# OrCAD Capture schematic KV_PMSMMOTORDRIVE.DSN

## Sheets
1 TITLE PAGE: title: FRDM-MC-LVPMSM; rev: X1; company: Freescale Semiconductor; note: SCH-XXXXX PDF: SPF-XXXXX; note: 6501 William Cannon Drive West; note: Austin, TX 78735-8598
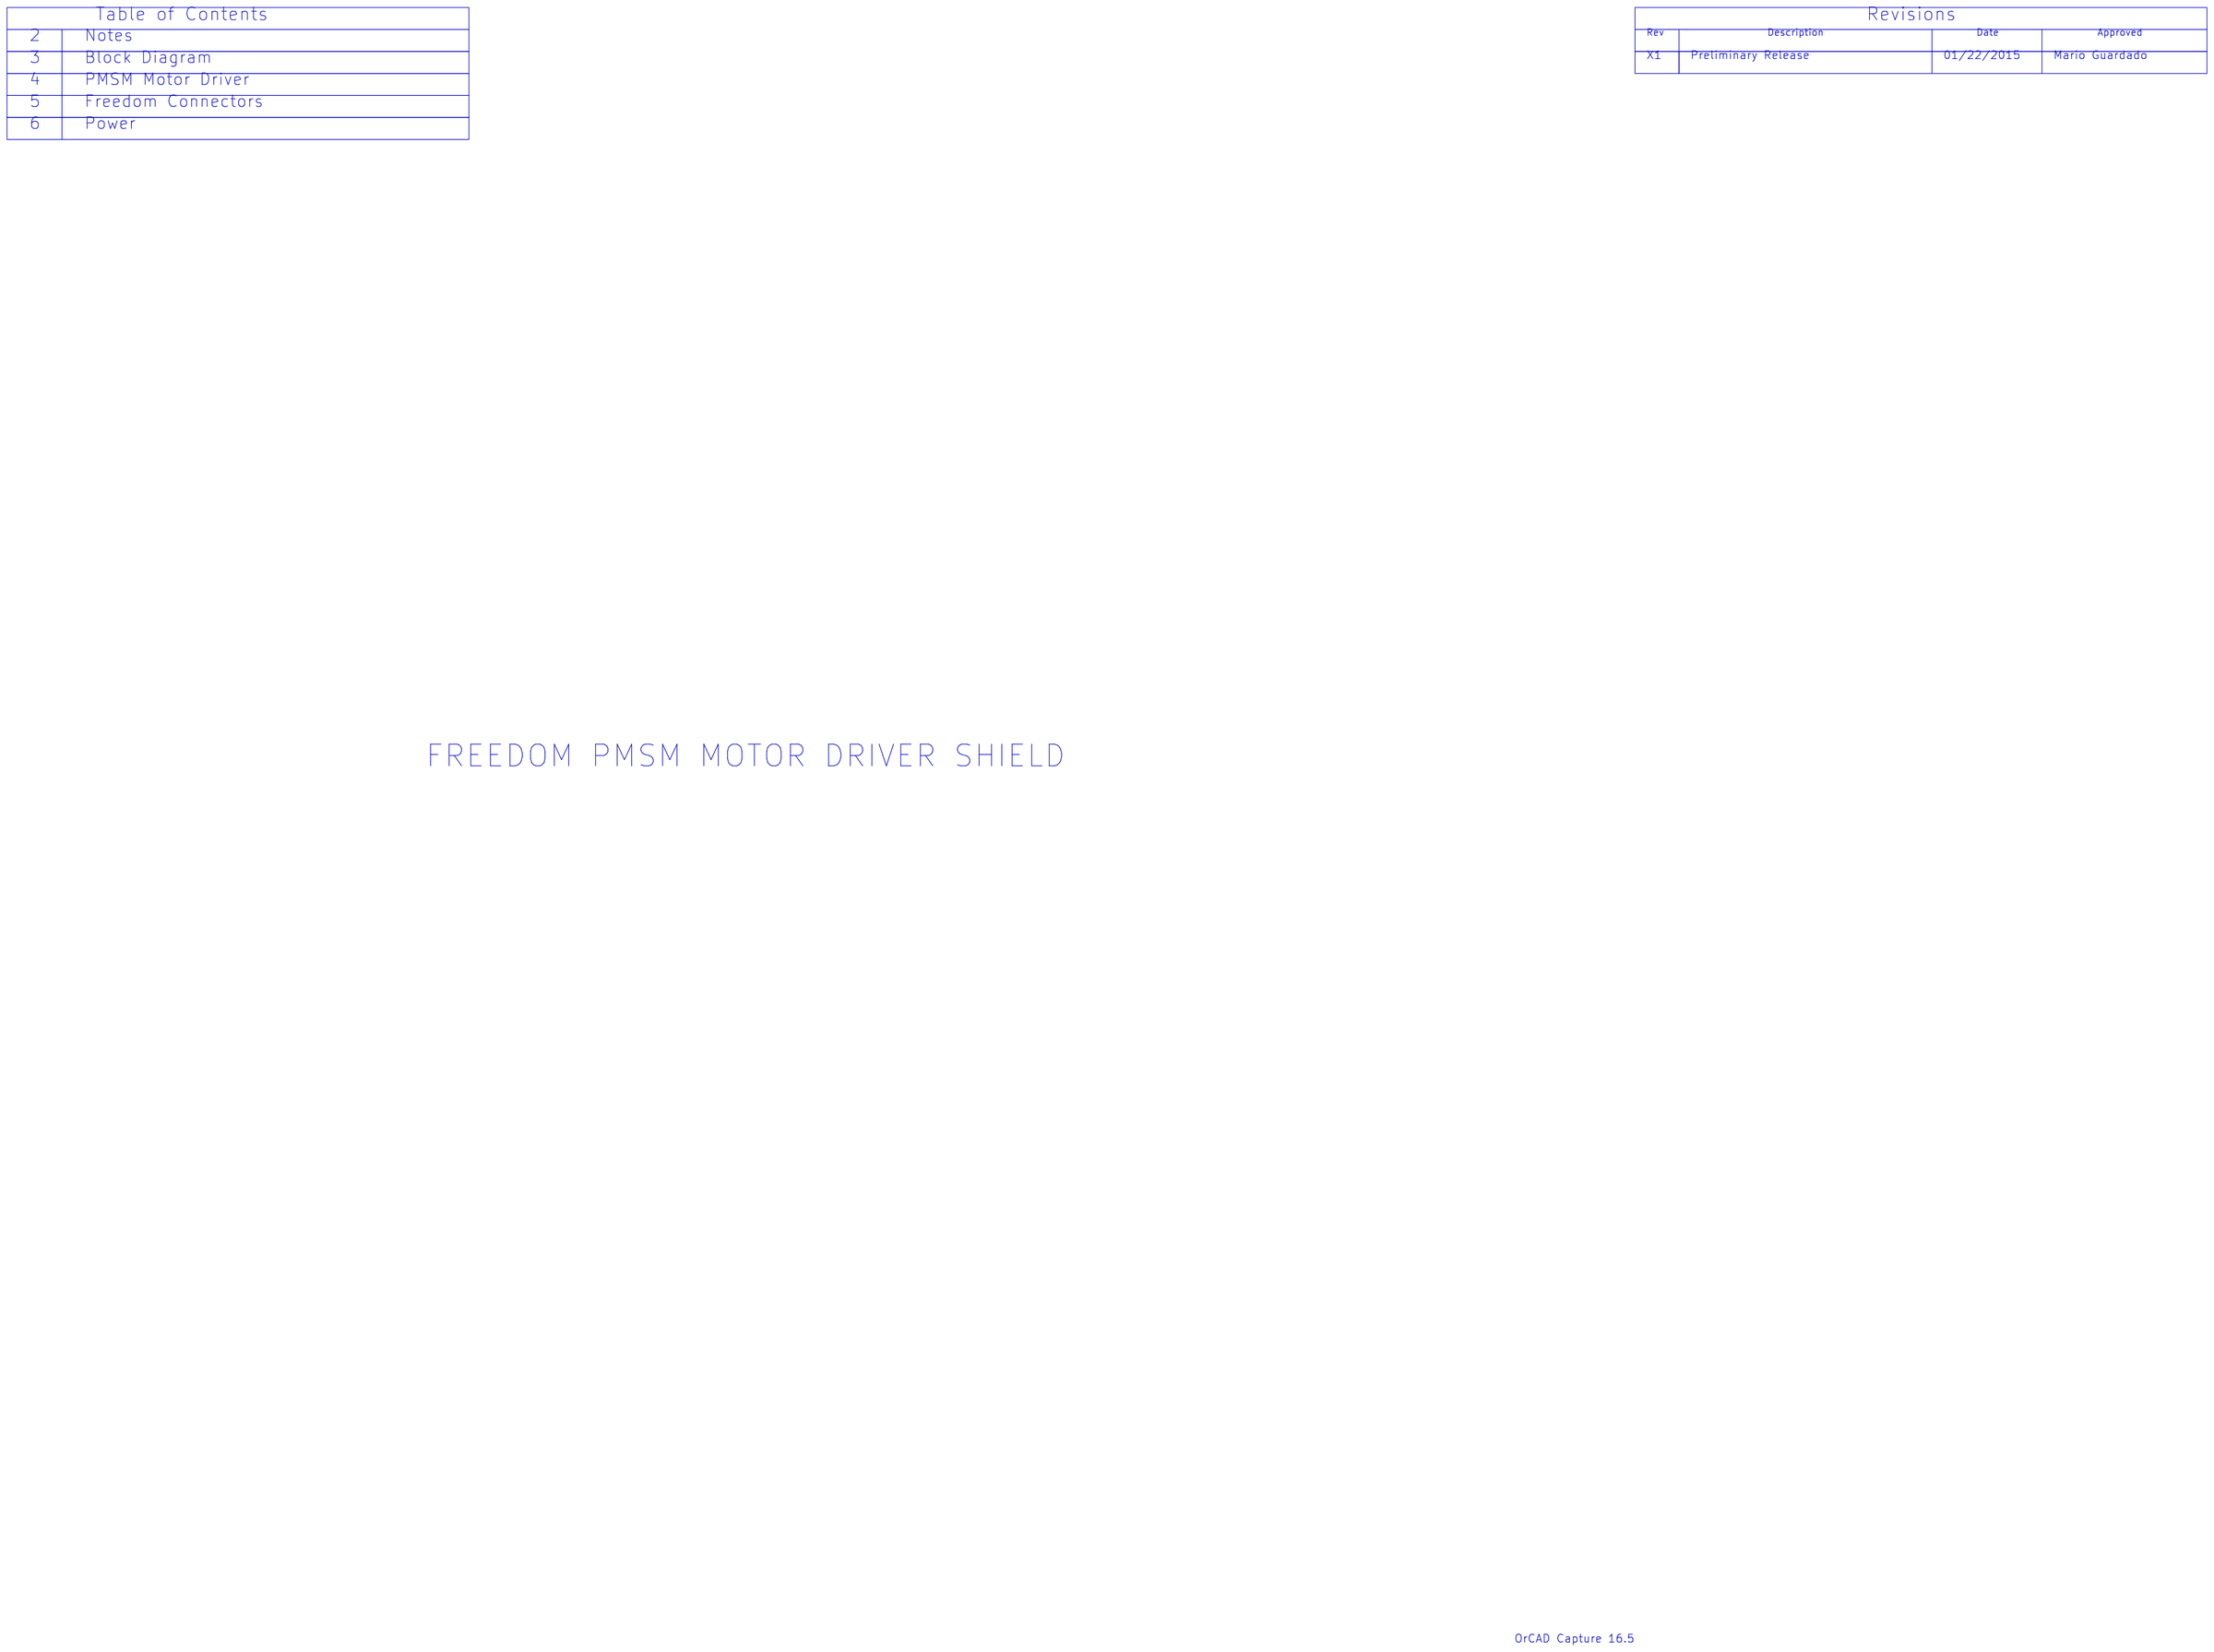
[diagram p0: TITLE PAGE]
2 NOTES
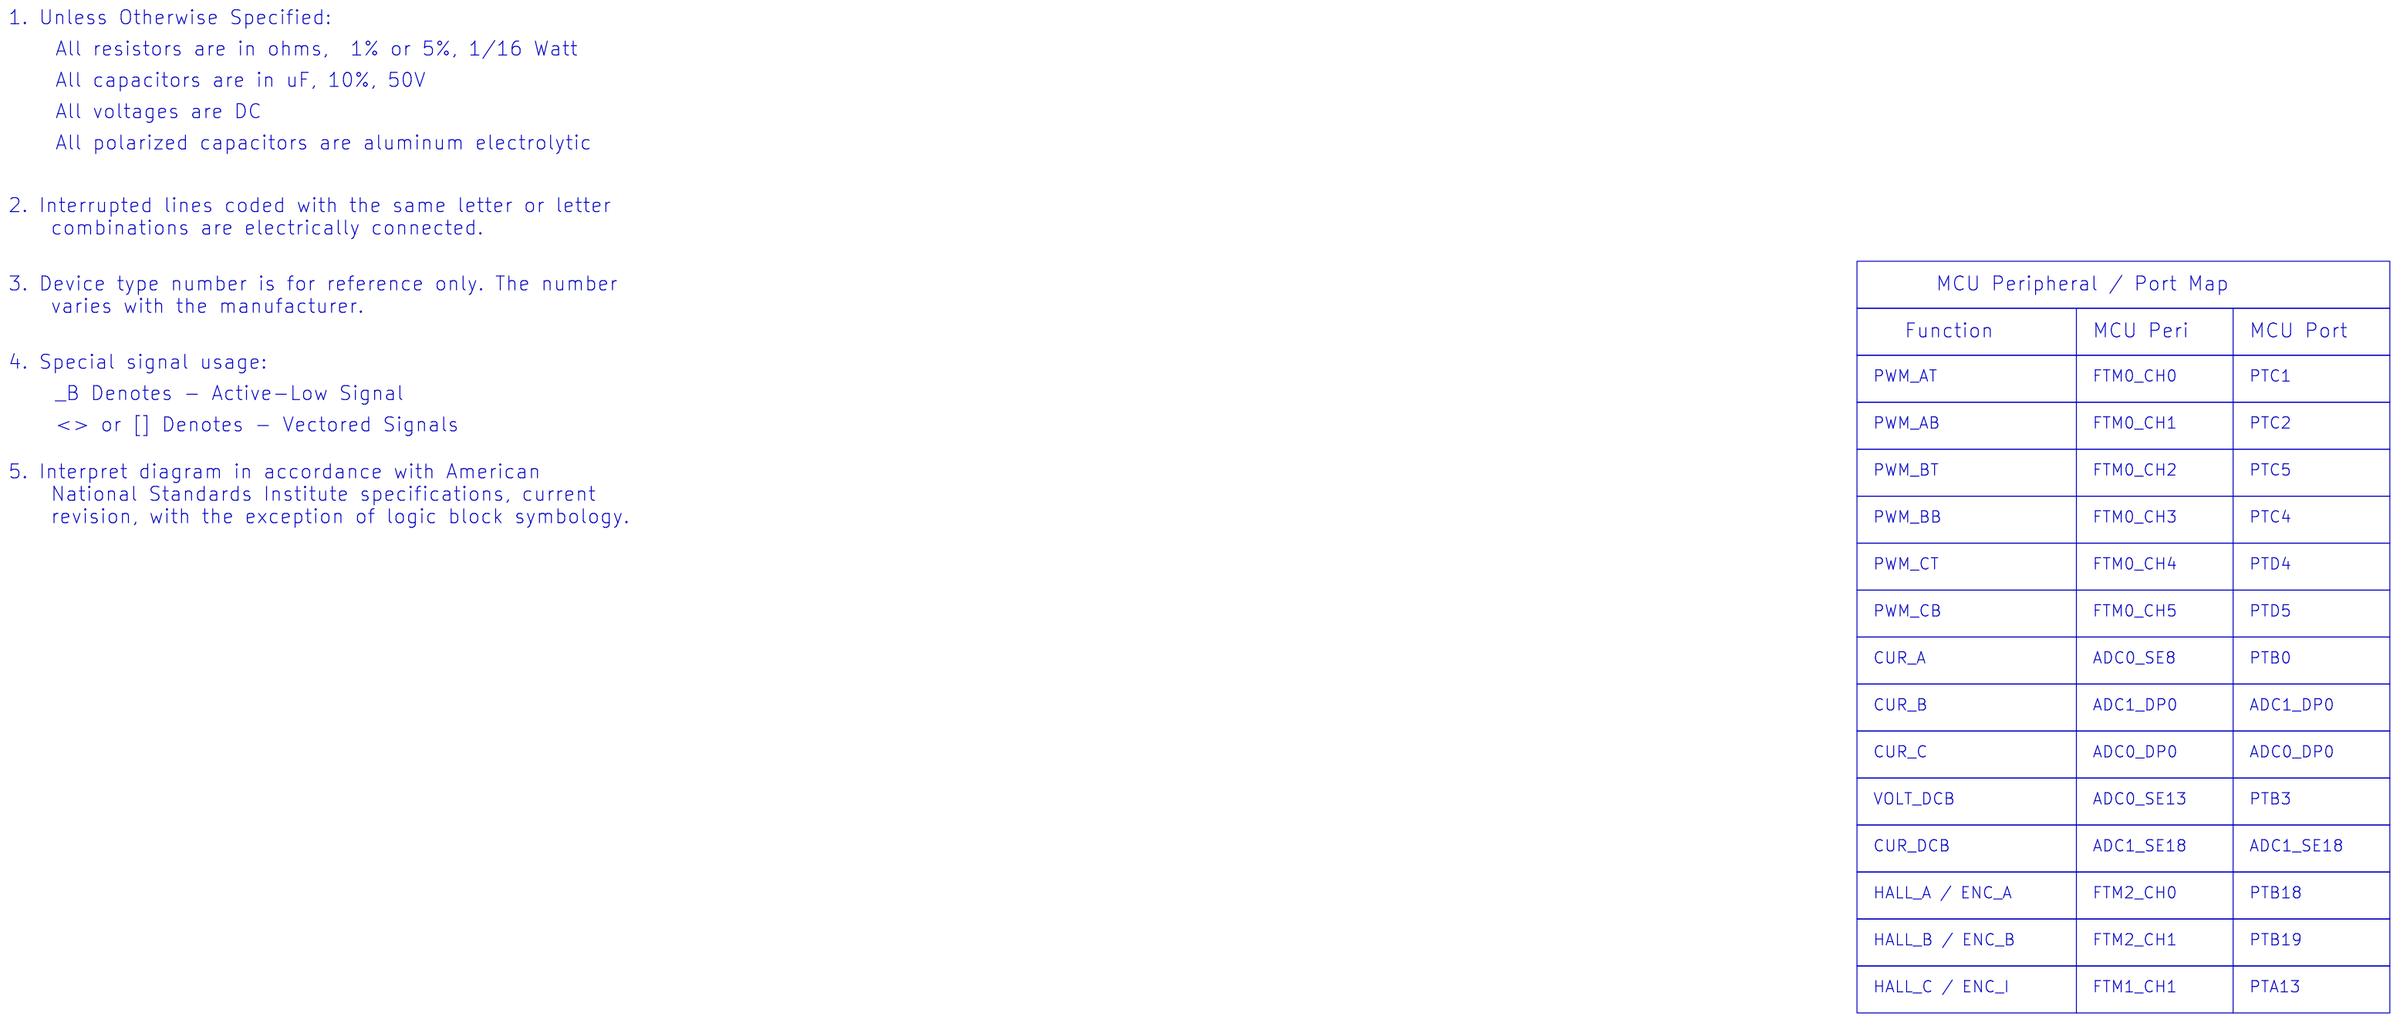
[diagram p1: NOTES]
3 BLOCK DIAGRAM
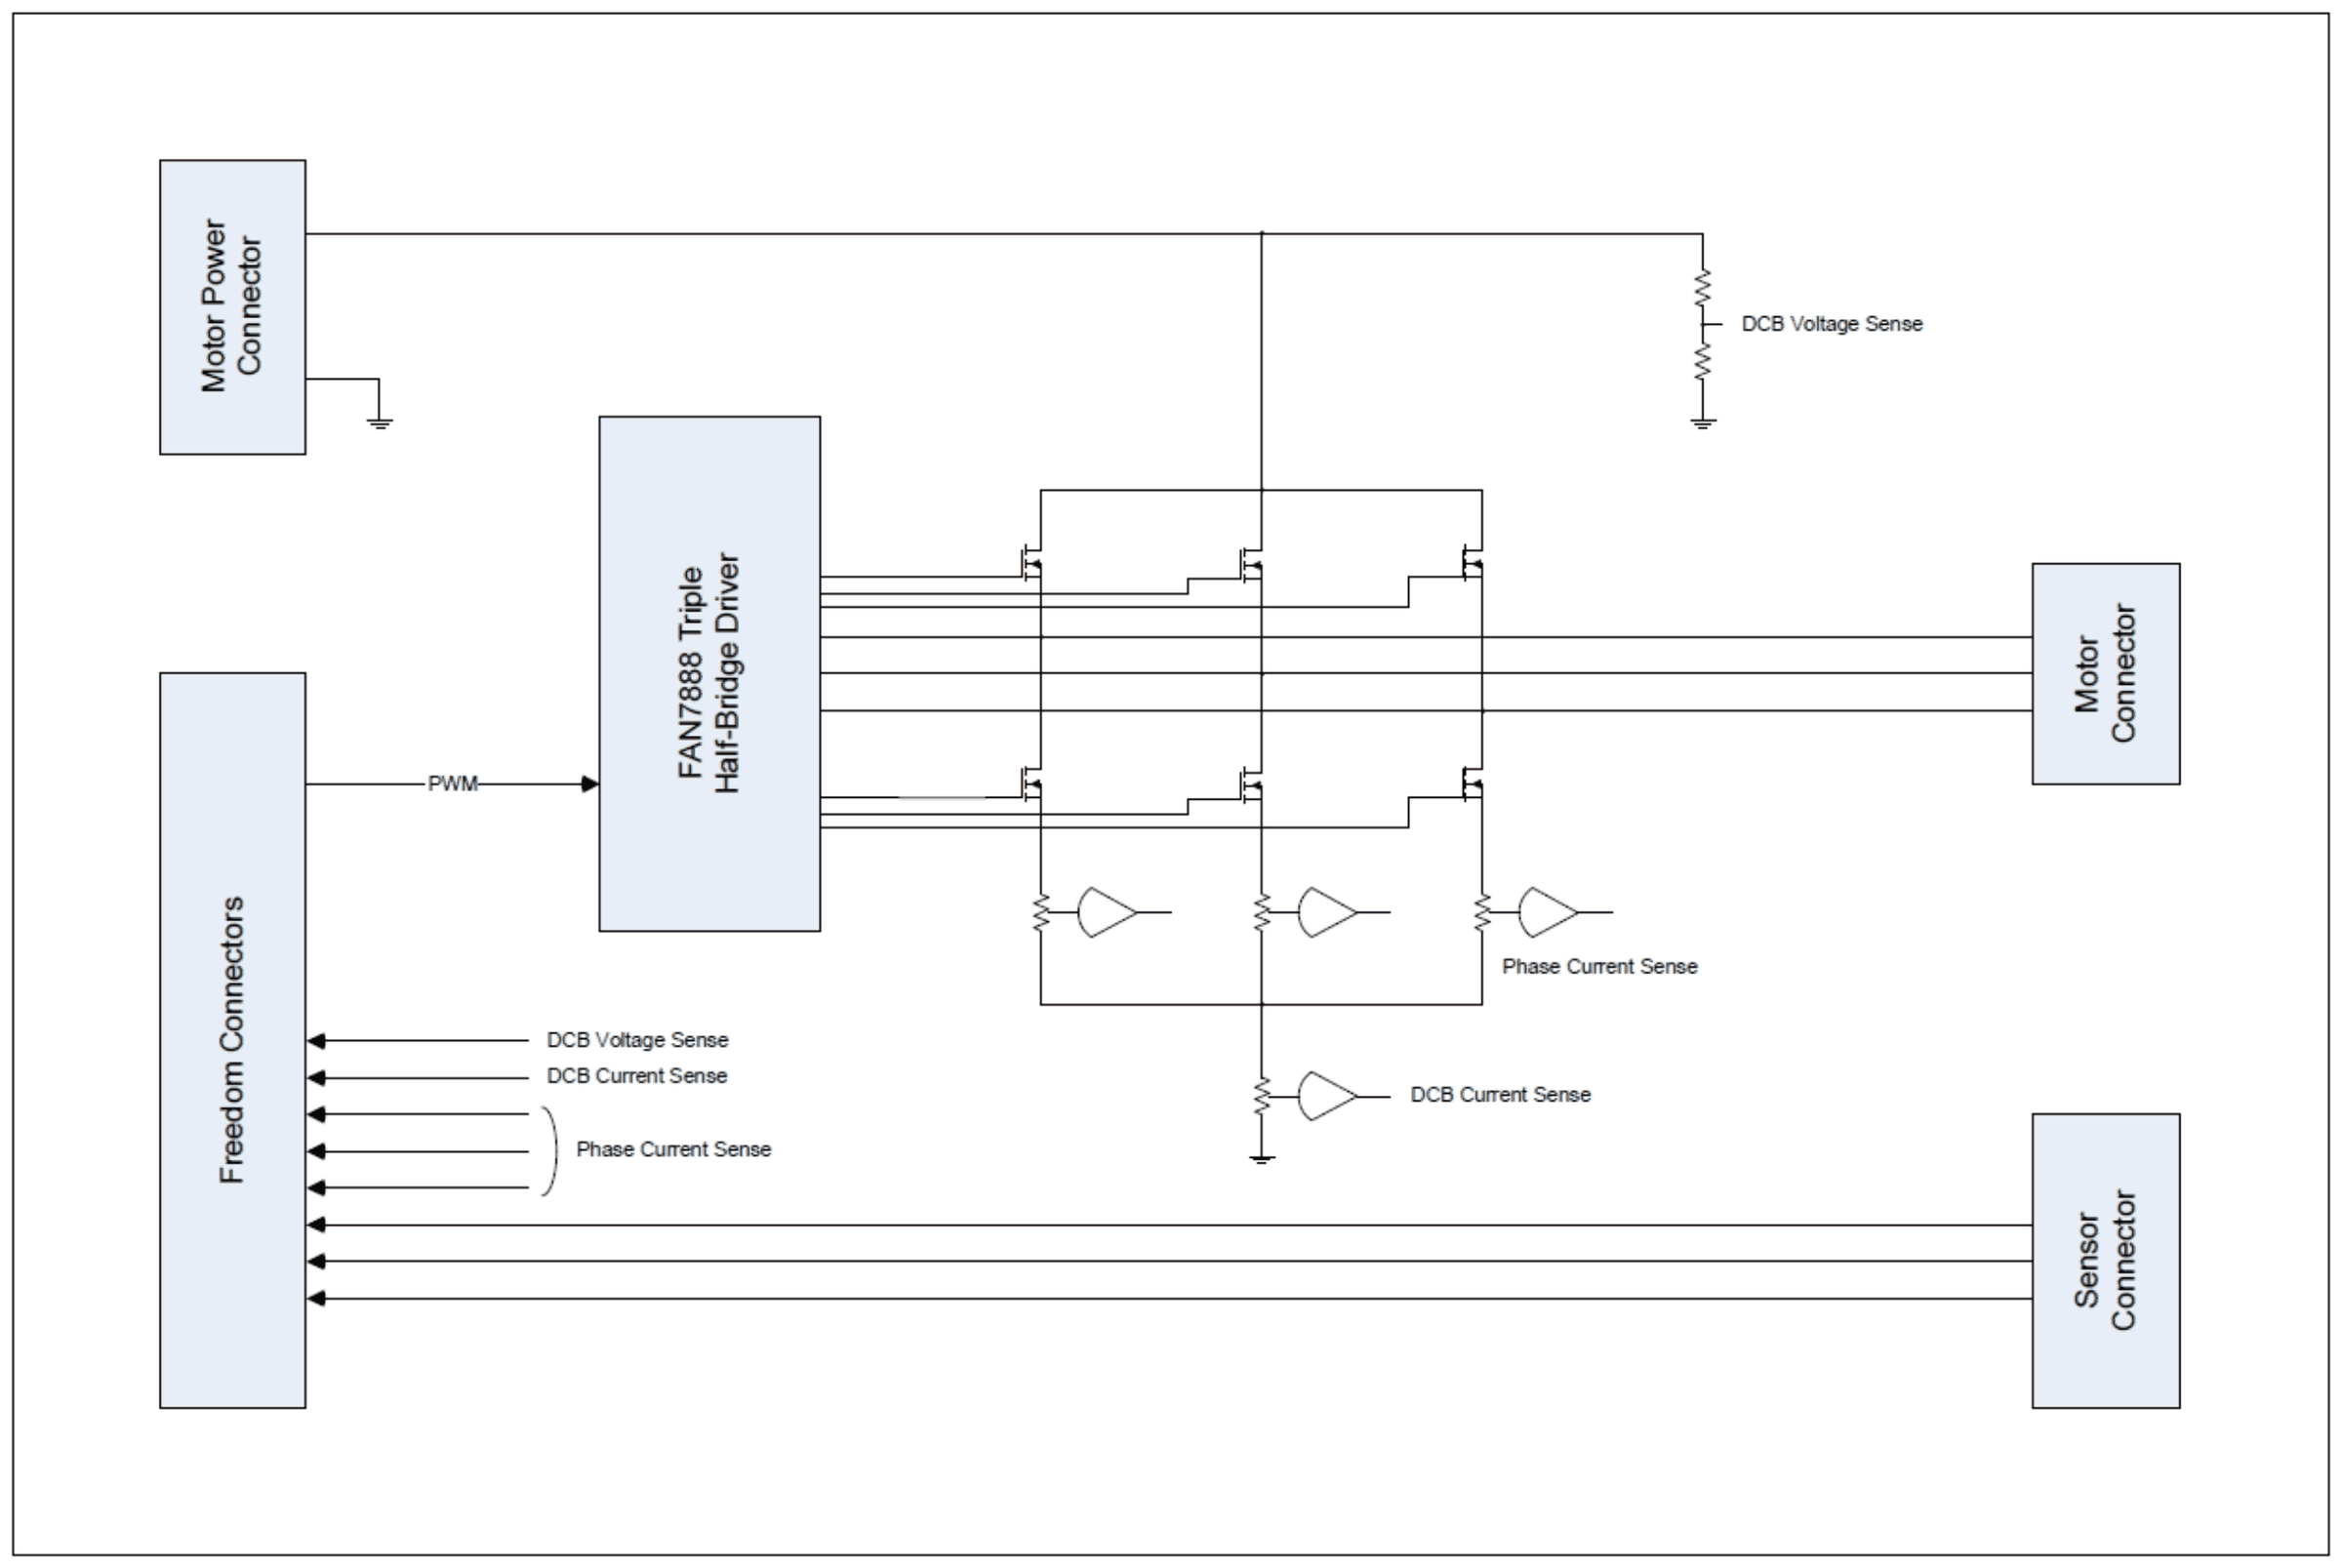
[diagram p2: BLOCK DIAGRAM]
4 MOTOR DRIVE: size C
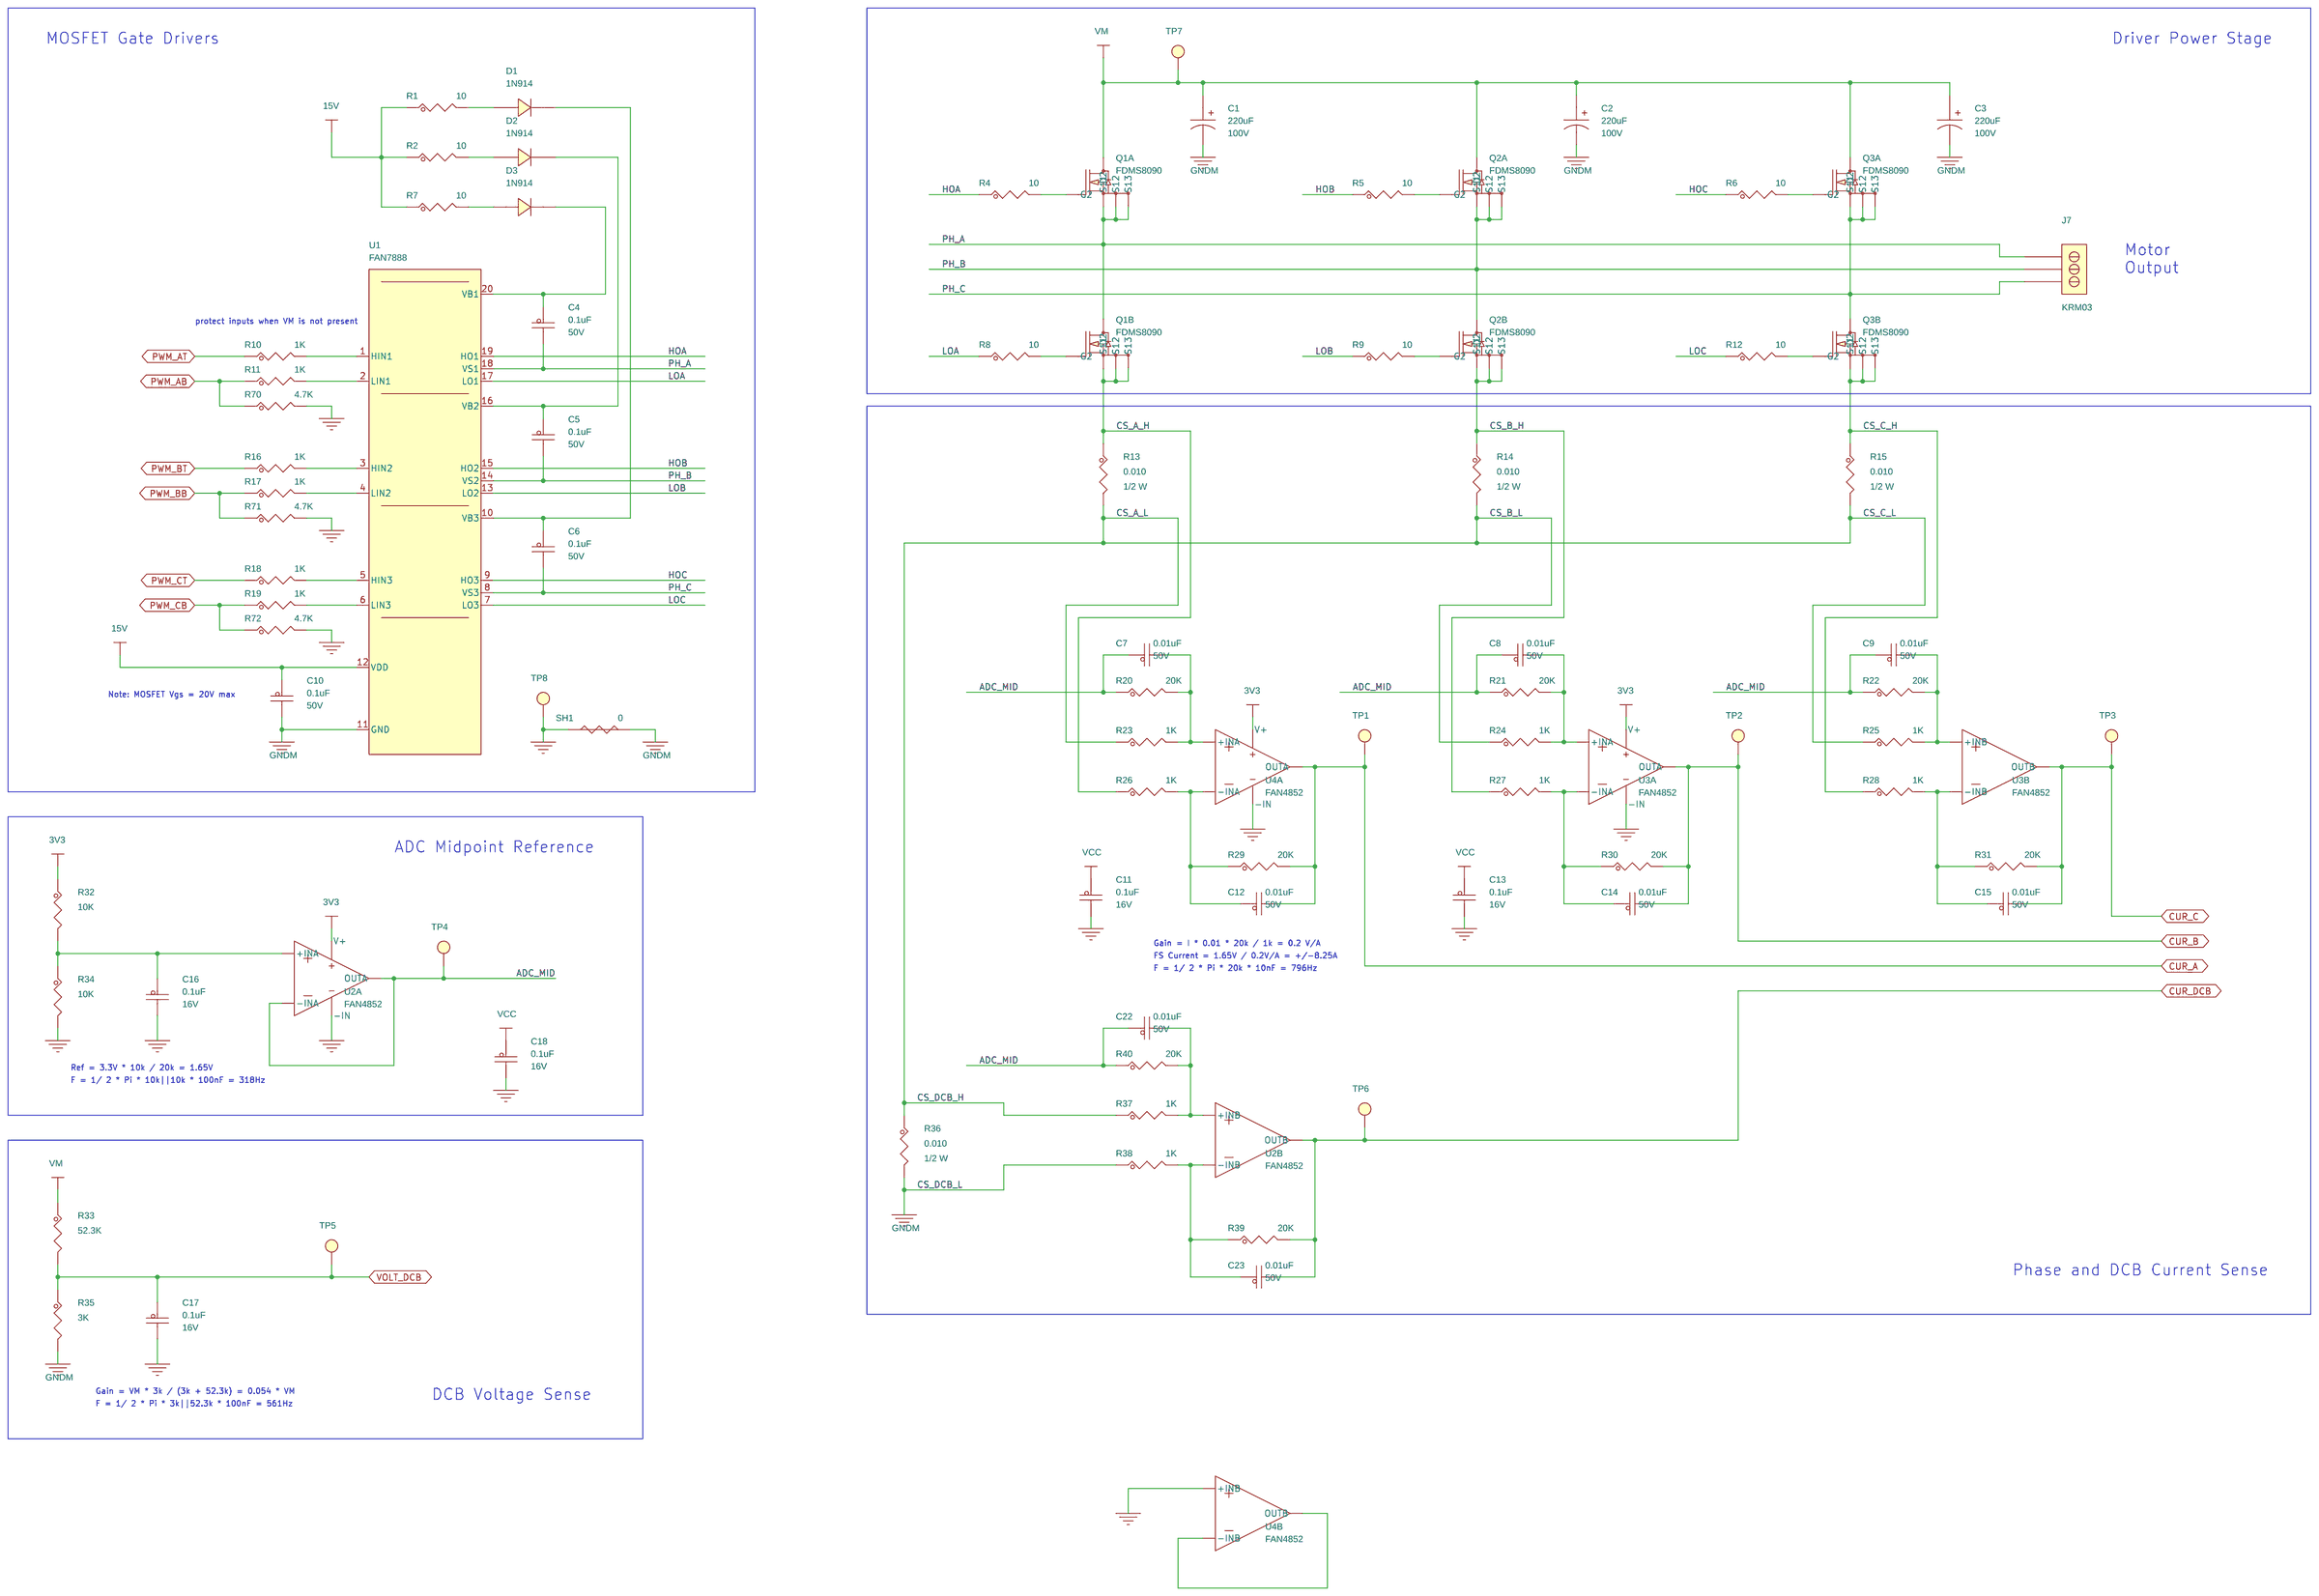
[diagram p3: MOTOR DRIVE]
5 MCU INTERFACE: size C
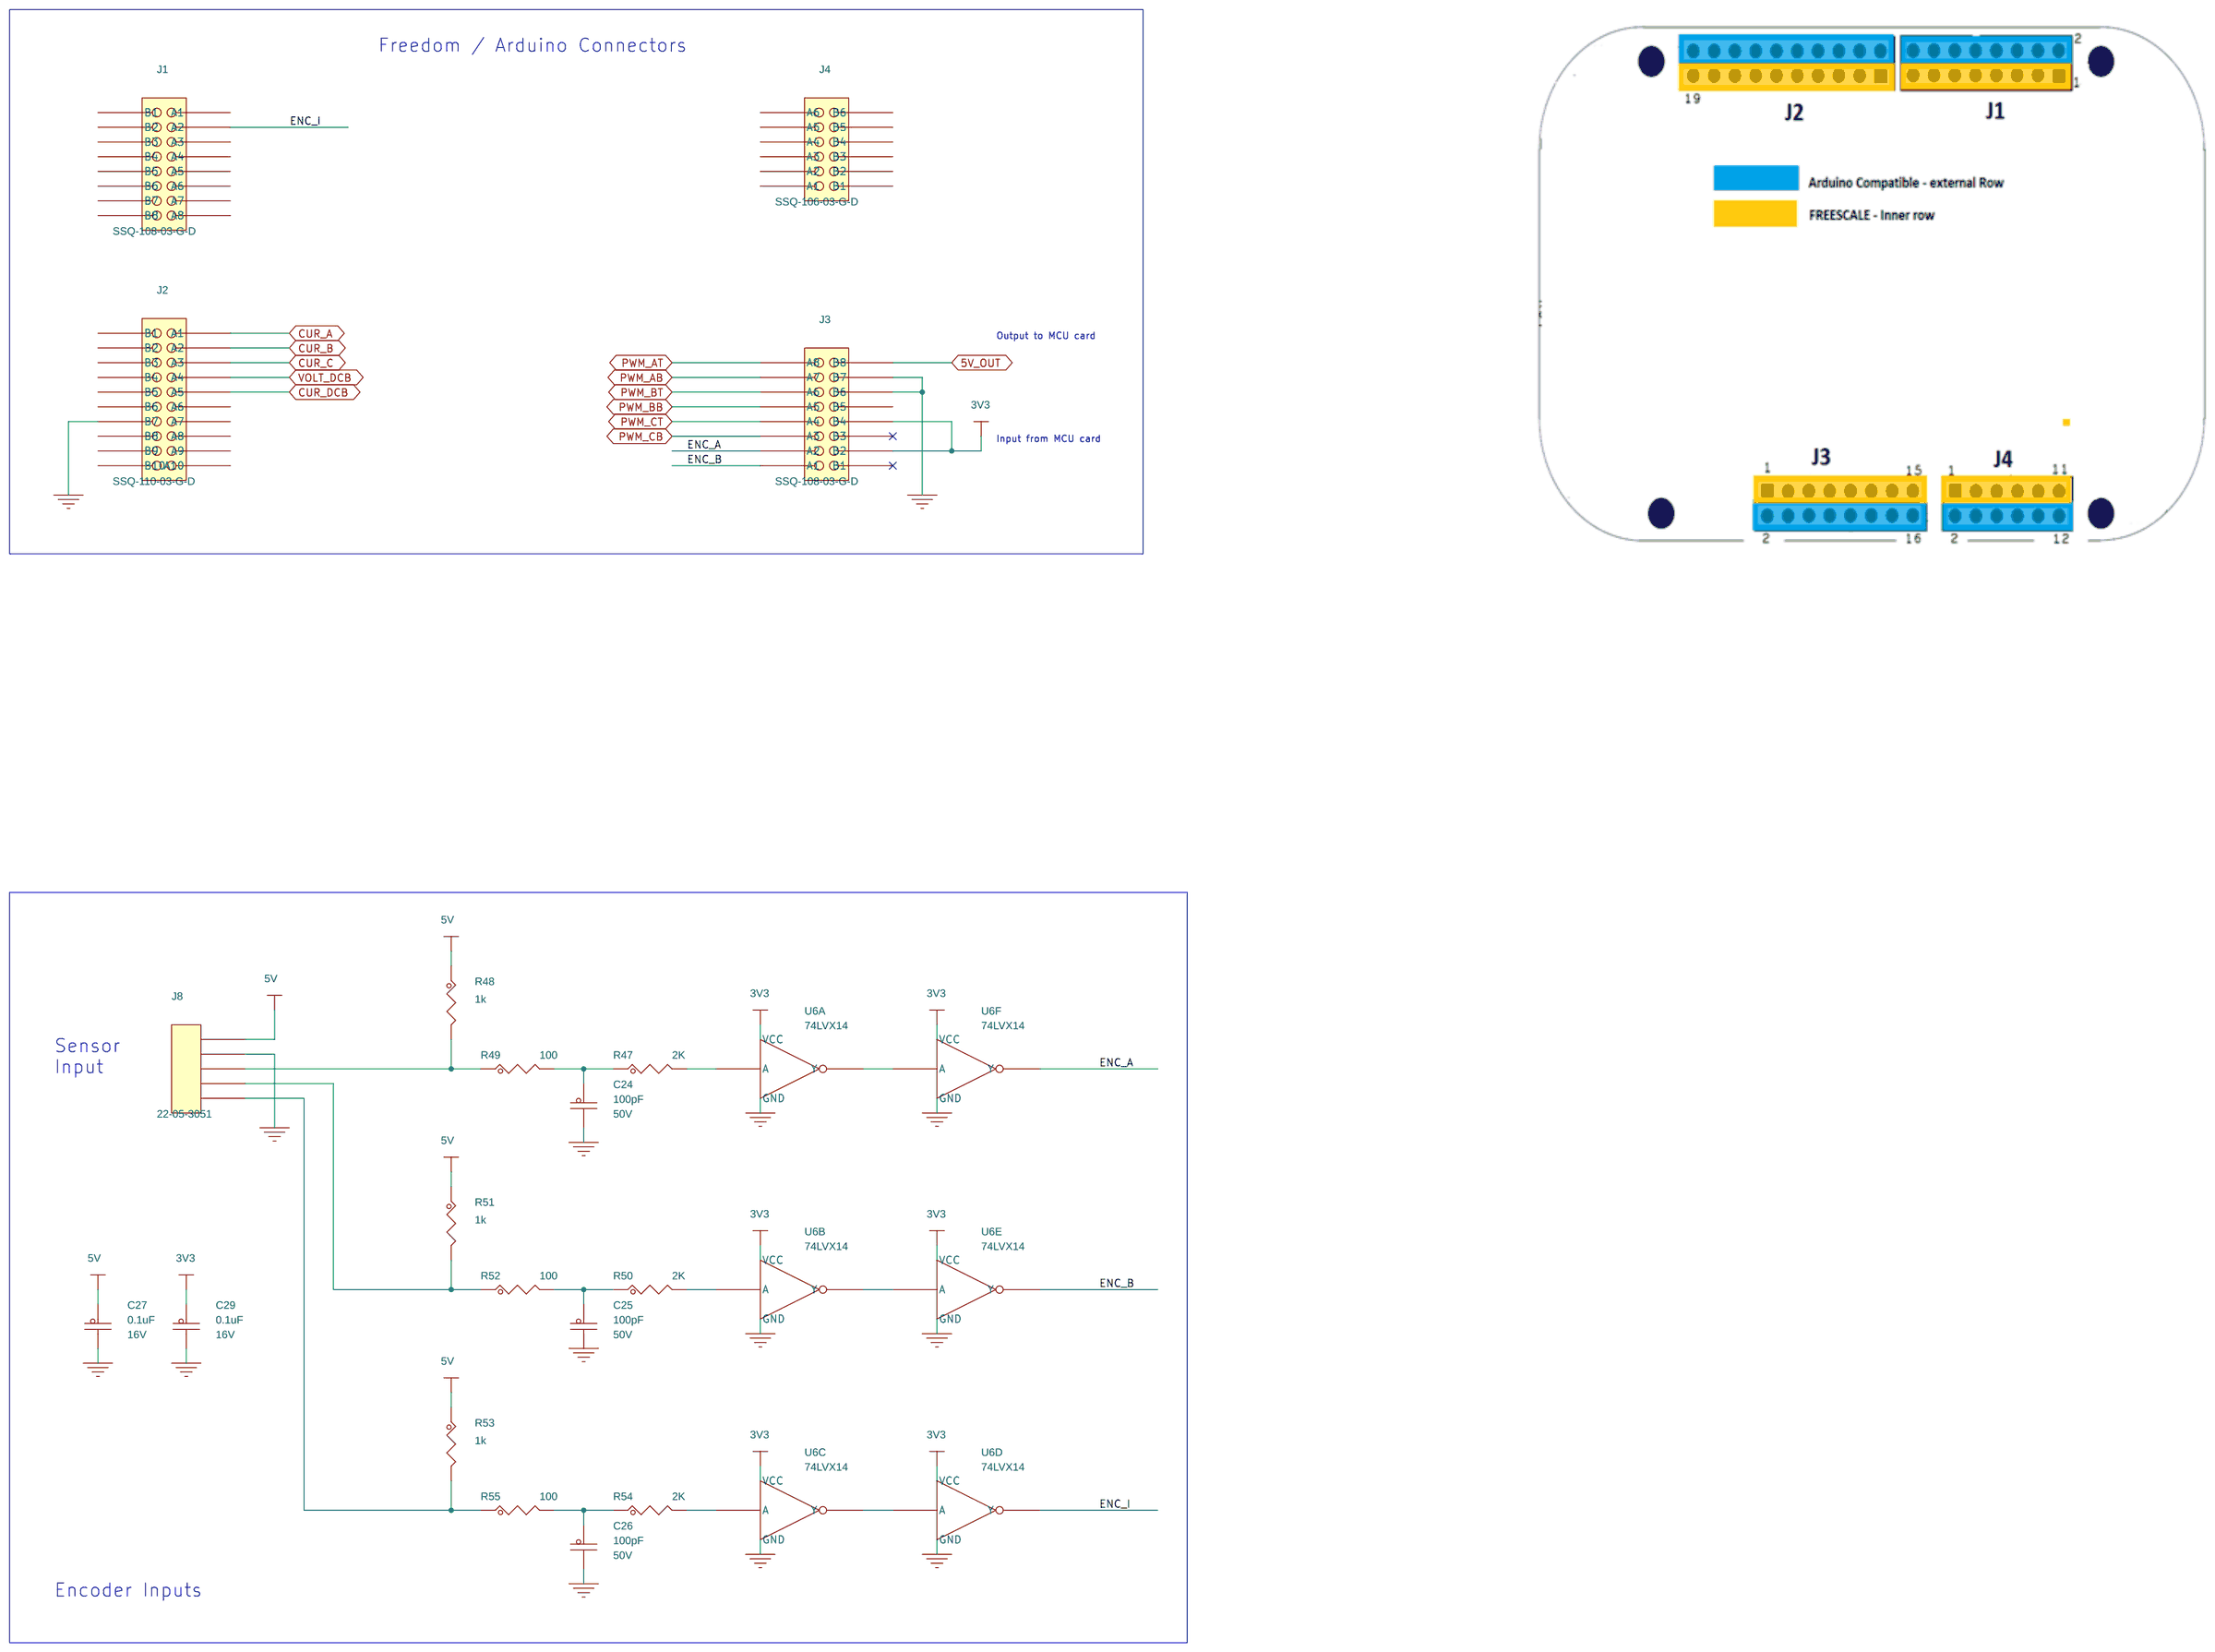
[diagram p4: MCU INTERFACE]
6 POWER: size C
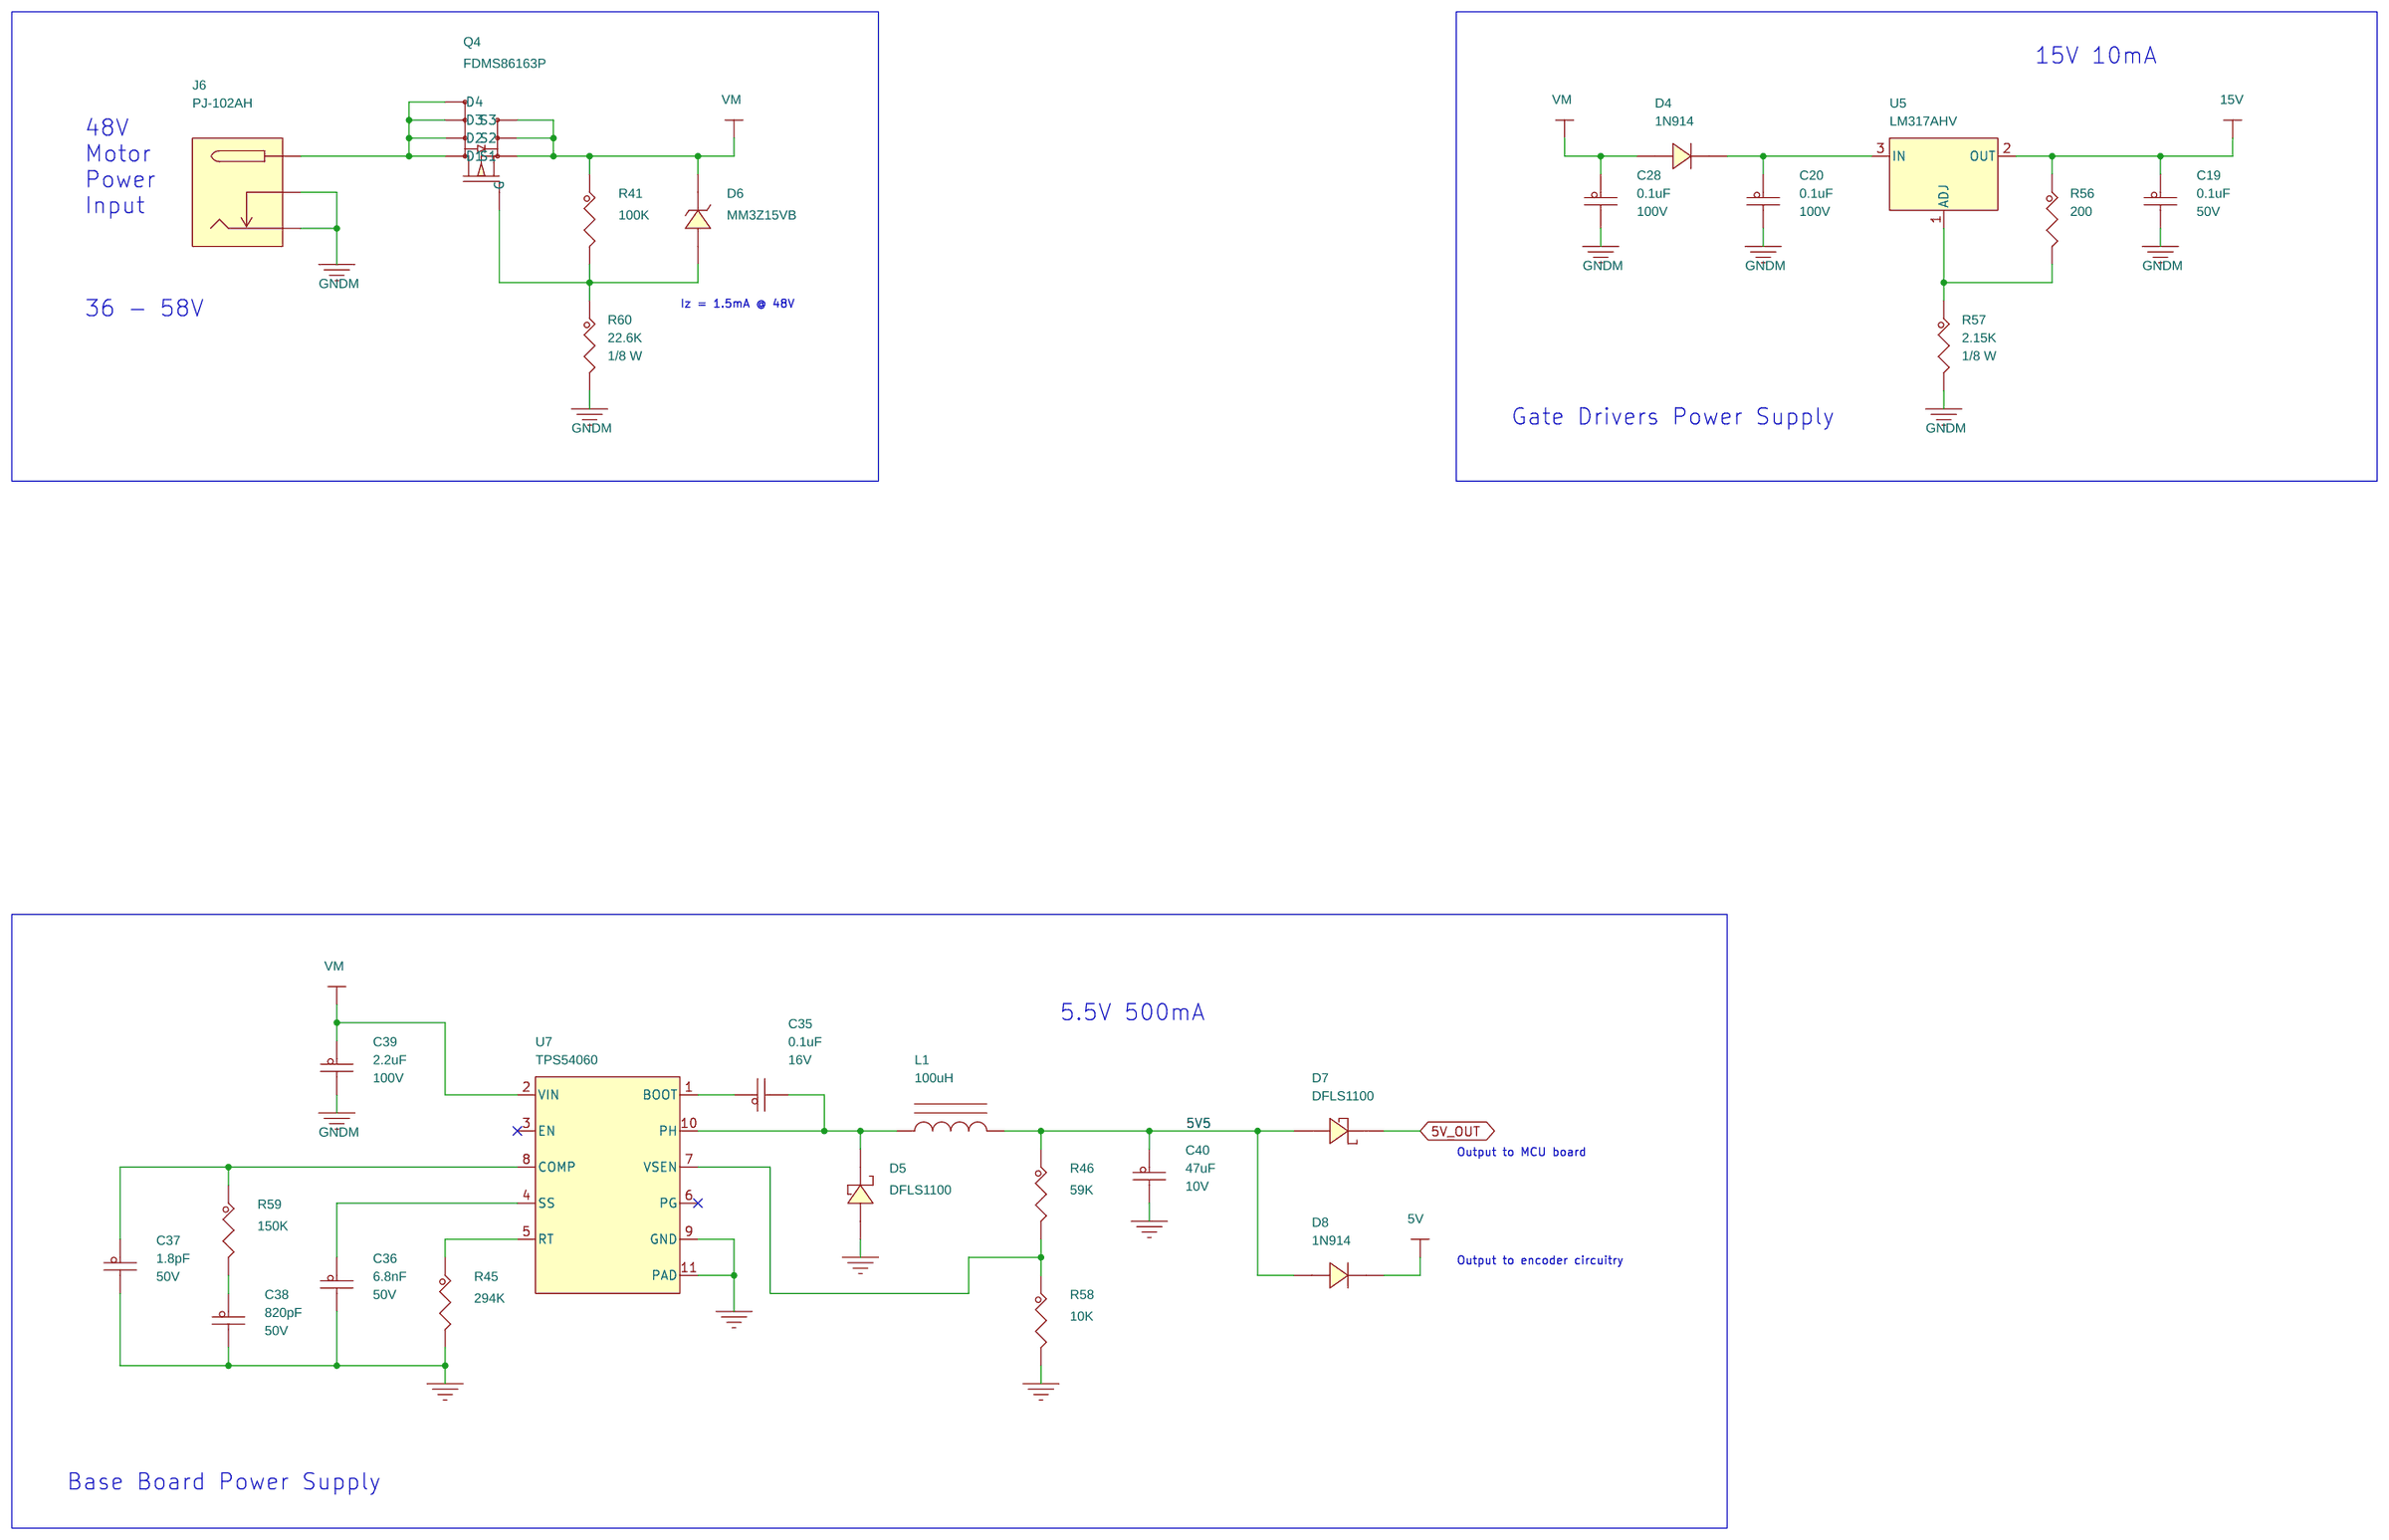
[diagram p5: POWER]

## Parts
sheet MCU INTERFACE
C24  100pF  [cc0402_25]
C25  100pF  [cc0402_25]
C26  100pF  [cc0402_25]
C27  0.1uF  [cc0402_25]
C29  0.1uF  [cc0402_25]
J1  SSQ-108-03-G-D  [SAMTEC_SSQ-108-03-G-D]
J2  SSQ-110-03-G-D  [SAMTEC_SSQ-110-03-G-D]
J3  SSQ-108-03-G-D  [SAMTEC_SSQ-108-03-G-D]
J4  SSQ-106-03-G-D  [SAMTEC_SSQ-106-03-G-D]
J8  22-05-3051  [CON_22-05-3051]
R47  2K  [rc0402_25]
R48  1k  [rc0402_25]
R49  100  [rc0402_25]
R50  2K  [rc0402_25]
R51  1k  [rc0402_25]
R52  100  [rc0402_25]
R53  1k  [rc0402_25]
R54  2K  [rc0402_25]
R55  100  [rc0402_25]
U6  74LVX14  [sop65p640x120-14n]  (sections A,B,C,D,E,F)
sheet MOTOR DRIVE
C1  220uF  [CAPRD_12p5x20mm]
C2  220uF  [CAPRD_12p5x20mm]
C3  220uF  [CAPRD_12p5x20mm]
C4  0.1uF  [cc0603_ov]
C5  0.1uF  [cc0603_ov]
C6  0.1uF  [cc0603_ov]
C7  0.01uF  [cc0402_25]
C8  0.01uF  [cc0402_25]
C9  0.01uF  [cc0402_25]
C10  0.1uF  [cc0603_ov]
C11  0.1uF  [cc0402_25]
C12  0.01uF  [cc0402_25]
C13  0.1uF  [cc0402_25]
C14  0.01uF  [cc0402_25]
C15  0.01uF  [cc0402_25]
C16  0.1uF  [cc0402_25]
C17  0.1uF  [cc0402_25]
C18  0.1uF  [cc0402_25]
C22  0.01uF  [cc0402_25]
C23  0.01uF  [cc0402_25]
D1  1N914  [SODFL2513x100N]
D2  1N914  [SODFL2513x100N]
D3  1N914  [SODFL2513x100N]
J7  KRM03  [CON_KRM03]
Q1  FDMS8090  [POWER56-10]  (sections A,B)
Q2  FDMS8090  [POWER56-10]  (sections A,B)
Q3  FDMS8090  [POWER56-10]  (sections A,B)
R1  10  [rc0402_25]
R2  10  [rc0402_25]
R4  10  [rc0402_25]
R5  10  [rc0402_25]
R6  10  [rc0402_25]
R7  10  [rc0402_25]
R8  10  [rc0402_25]
R9  10  [rc0402_25]
R10  1K  [rc0402_25]
R11  1K  [rc0402_25]
R12  10  [rc0402_25]
R13  0.010  [rc1206_ov]
R14  0.010  [rc1206_ov]
R15  0.010  [rc1206_ov]
R16  1K  [rc0402_25]
R17  1K  [rc0402_25]
R18  1K  [rc0402_25]
R19  1K  [rc0402_25]
R20  20K  [rc0402_25]
R21  20K  [rc0402_25]
R22  20K  [rc0402_25]
R23  1K  [rc0402_25]
R24  1K  [rc0402_25]
R25  1K  [rc0402_25]
R26  1K  [rc0402_25]
R27  1K  [rc0402_25]
R28  1K  [rc0402_25]
R29  20K  [rc0402_25]
R30  20K  [rc0402_25]
R31  20K  [rc0402_25]
R32  10K  [rc0402_25]
R33  52.3K  [rc0402_25]
R34  10K  [rc0402_25]
R35  3K  [rc0402_25]
R36  0.010  [rc1206_ov]
R37  1K  [rc0402_25]
R38  1K  [rc0402_25]
R39  20K  [rc0402_25]
R40  20K  [rc0402_25]
R70  4.7K  [rc0402_25]
R71  4.7K  [rc0402_25]
R72  4.7K  [rc0402_25]
SH1  0  [rc0402_25_ct]
TP1  TP  [TP_TH_040]
TP2  TP  [TP_TH_040]
TP3  TP  [TP_TH_040]
TP4  TP  [TP_TH_040]
TP5  TP  [TP_TH_040]
TP6  TP  [TP_TH_040]
TP7  TP  [TP_TH_040]
TP8  TP  [TP_TH_040]
U1  FAN7888  [soic127p1032x265-20n]
U2  FAN4852  [sop65p490x110-8n]  (sections A,B)
U3  FAN4852  [sop65p490x110-8n]  (sections A,B)
U4  FAN4852  [sop65p490x110-8n]  (sections A,B)
sheet POWER
C19  0.1uF  [cc0603_ov]
C20  0.1uF  [cc0805_ov]
C28  0.1uF  [cc0805_ov]
C35  0.1uF  [cc0402_25]
C36  6.8nF  [cc0402_25]
C37  1.8pF  [cc0402_25]
C38  820pF  [cc0402_25]
C39  2.2uF  [cc1210_ov]
C40  47uF  [cc1206_ov]
D4  1N914  [SODFL2513x100N]
D5  DFLS1100  [SODFL3718X100N]
D6  MM3Z15VB  [SODFL2513X100N]
D7  DFLS1100  [SODFL3718X100N]
D8  1N914  [SODFL2513x100N]
J6  PJ-102AH  [CON_PJ-102AH]
L1  100uH  [IND_SRN8040]
Q4  FDMS86163P  [POWER56-8]
R41  100K  [rc0402_25]
R45  294K  [rc0402_25]
R46  59K  [rc0402_25]
R56  200  [rc0402_25]
R57  2.15K  [rc0805_ov]
R58  10K  [rc0402_25]
R59  150K  [rc0402_25]
R60  22.6K  [rc0805_ov]
U5  LM317AHV  [TO-220]
U7  TPS54060  [SOP50P490X110-11N]

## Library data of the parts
C24-C26 = CAP_NP: CAP, CER 100PF 50V 5% C0G 0402; MFG_NAME01: KEMET; MFG_PN01: C0402C101J5GACTU; VOLTAGE: 50V
C11 C13 C16-C18 C27 C29 C35 = CAP_NP: CAP, CER 0.1UF 16V 10% X7R 0402; MFG_NAME01: KEMET; MFG_PN01: C0402C104K4RACTU; VOLTAGE: 16V
J1 J3 = CONN_2x8
J2 = CONN_2x10
J4 = CONN_2x6
J8 = CON5: Connector, 5-pin, 100mil; MFG_NAME01: Molex
R47 R50 R54 = RES: RES, MF 2K 1/16W 1% 0402; MFG_PN01: CRCW04022K00FKED
R10 R11 R16-R19 R23-R28 R37 R38 R48 R51 R53 = RES: RES, MF 1K 1/16W 1% 0402; MFG_PN01: CRCW04021K00FKED
R49 R52 R55 = RES: RES, MF 100 1/16W 1% 0402; MFG_PN01: CRCW0402100RFKED
U6 = 74LVX14
C1-C3 = CAP_POL: CAP, POL, 220UF 100V 20%; CLASS: DISCRETE; MFG_NAME01: NICHICON; MFG_PN01: UVK2A221MHD; VOLTAGE: 100V
C4-C6 C10 C19 = CAP_NP: CAP, CER 0.1UF 50V 10% X7R 0603; MFG_NAME01: KEMET; MFG_PN01: C0603C104K5RACTU; VOLTAGE: 50V
C7-C9 C12 C14 C15 C22 C23 = CAP_NP: CAP, CER 0.01UF 50V 10% X7R 0402; MFG_NAME01: KEMET; MFG_PN01: C0402C103K5RACTU; VOLTAGE: 50V
D1-D4 D8 = 1N914BWS
J7 = KRM03
Q1-Q3 = FDMS8090
R1 R2 R4-R9 R12 = RES: MFG_PN01: CRCW040210R0JNED
R13-R15 R36 = RES: RES, MF 0.01 1/2W 1% 1206; MFG_NAME01: SEI; MFG_PN01: CSR1206FT10L0; Power: 1/2 W
R20-R22 R29-R31 R39 R40 = RES: RES, MF 20K 1/16W 1% 0402; MFG_PN01: CRCW040220K0FKED
R32 R34 R58 = RES: RES, MF 10K 1/16W 1% 0402; MFG_PN01: CRCW040210K0FKED
R33 = RES: RES, MF 52.3K 1/16W 1% 0402; MFG_PN01: CRCW040252K3FKED
R35 = RES: RES, MF 3K 1/16W 1% 0402; MFG_PN01: CRCW04023K00FKED
R70-R72 = RES: RES, MF 4.7K 1/16W 5% 0402; MFG_PN01: CRCW04024K70JNED
SH1 = SH_RES: CUT TRACE RESISTOR; FPLIST: RC0402_25_CT,RC0402_HD_CT,0402_CC_CT; MFG_NAME01: NOTACOMPONENT; MFG_PN01: NOTACOMPONENT
TP1-TP8 = TP
U1 = FAN7888
U2-U4 = FAN4852
C20 C28 = CAP_NP: CAP, CER 0.1UF 100V 10% X7R 0805; MFG_NAME01: KEMET; MFG_PN01: C0805C104K1RACTU; VOLTAGE: 100V
C36 = CAP_NP: CAP, CER 6.8NF 50V 10% X7R 0402; MFG_NAME01: KEMET; MFG_PN01: C0402C682K5RACTU; VOLTAGE: 50V
C37 = CAP_NP: CAP, CER 1.8PF 50V C0G 0402; MFG_NAME01: KEMET; MFG_PN01: C0402C189C5GACTU; VOLTAGE: 50V
C38 = CAP_NP: CAP, CER 820PF 50V 5% C0G 0402; MFG_NAME01: KEMET; MFG_PN01: C0402C821J5GACTU; VOLTAGE: 50V
C39 = CAP_NP: CAP, CER 2.2UF 100V 10% X7R 1210; MFG_NAME01: TDK; MFG_PN01: C3225X7R2A225K230AB; VOLTAGE: 100V
C40 = CAP_NP: CAP, CER 47UF 10V 20% X5R 1206; MFG_NAME01: MURATA; MFG_PN01: GRM31CR61A476ME15L; VOLTAGE: 10V
D5 D7 = DFLS1100
D6 = MM3Z15VB: DIODE, ZENER, 15V 2% 200mW
J6 = PJ-102AH: CONNECTOR, BARREL
L1 = SRN8040: INDUCTOR, 100UH; MFG_PN01: SRN8040-101M
Q4 = FDMS86163P
R41 = RES: RES, MF 100K 1/16W 1% 0402; MFG_PN01: CRCW0402100KFKED
R45 = RES: RES, MF 294K 1/16W 1% 0402; MFG_PN01: CRCW0402294KFKED
R46 = RES: RES, MF 59K 1/16W 1% 0402; MFG_PN01: CRCW040259K0FKED
R56 = RES: RES, MF 200 1/16W 5% 0402; MFG_PN01: CRCW0402200RFKED
R57 = RES: RES, MF 2.15K 1/8W 1% 0805; MFG_PN01: CRCW08052K15FKEA; Power: 1/8 W
R59 = RES: RES, MF 150K 1/16W 1% 0402; MFG_PN01: CRCW0402150KFKED
R60 = RES: RES, MF 22.6K 1/8W 1% 0805; MFG_PN01: CRCW080522K6FKEA; Power: 1/8 W
U5 = LM317AHV: IC, LINEAR VOLTAGE REGULATOR ADJ; MFG_PN01: LM317AHVT
U7 = TPS54060

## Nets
3V3: C11.1 C13.1 C18.1 C29.1 J3.4(B2) J3.8(B4) R32.1 U2.8(V+) U3.8(V+) U4.8(V+) U6.14(VCC)
5V: C27.1 D8.C J8.1 R48.1 R51.1 R53.1
5V5: C40.1 D7.A D8.A L1.2 R46.1
5V_OUT: D7.C J3.16(B8)
15V: C10.1 C19.1 R1.1 R2.1 R7.1 R56.1 U1.12(VDD) U5.2(OUT)
GND: C11.2 C13.2 C16.2 C17.2 C18.2 C24.2 C25.2 C26.2 C27.2 C29.2 C36.2 C37.2 C38.2 C40.2 D5.A J2.14(B7) J3.12(B6) J3.14(B7) J8.2 R34.2 R45.2 R58.2 R70.2 R71.2 R72.2 SH1.1 TP8.1(TP) U2.4(-IN) U3.4(-IN) U4.4(-IN) U4.5(+INB) U6.7(GND) U7.9(GND) U7.11(PAD)
GNDM: C1.2(MINUS) C2.2(MINUS) C3.2(MINUS) C10.2 C19.2 C20.2 C28.2 C39.2 J6.2 J6.3 R35.2 R36.2 R38.1 R57.2 R60.2 SH1.2 U1.11(GND)
ADC_MID: C7.1 C8.1 C9.1 C22.1 R20.1 R21.1 R22.1 R40.1 TP4.1(TP) U2.1(OUTA) U2.2(-INA)
CS_A_H: Q1.5(S13) Q1.6(S12) Q1.7(S11) R13.1 R26.1
CS_A_L: R13.2 R14.2 R15.2 R23.1 R24.1 R25.1 R36.1 R37.1
CS_B_H: Q2.5(S13) Q2.6(S12) Q2.7(S11) R14.1 R27.1
CS_C_H: Q3.5(S13) Q3.6(S12) Q3.7(S11) R15.1 R28.1
CUR_A: C12.2 J2.1(A1) R29.2 TP1.1(TP) U4.1(OUTA)
CUR_B: C14.2 J2.3(A2) R30.2 TP2.1(TP) U3.1(OUTA)
CUR_C: C15.2 J2.5(A3) R31.2 TP3.1(TP) U3.7(OUTB)
CUR_DCB: C23.2 J2.9(A5) R39.2 TP6.1(TP) U2.7(OUTB)
ENC_A: J3.3(A2) U6.12(Y)
ENC_B: J3.1(A1) U6.10(Y)
ENC_I: J1.3(A2) U6.8(Y)
HOA: R4.1 U1.19(HO1)
HOB: R5.1 U1.15(HO2)
HOC: R6.1 U1.9(HO3)
LOA: R8.1 U1.17(LO1)
LOB: R9.1 U1.13(LO2)
LOC: R12.1 U1.7(LO3)
PH_A: C4.2 J7.1 Q1.2(S11) Q1.3(S12) Q1.4(S13) Q1.10(D2) U1.18(VS1)
PH_B: C5.2 J7.2 Q2.2(S11) Q2.3(S12) Q2.4(S13) Q2.10(D2) U1.14(VS2)
PH_C: C6.2 J7.3 Q3.2(S11) Q3.3(S12) Q3.4(S13) Q3.10(D2) U1.8(VS3)
PWM_AB: J3.13(A7) R11.1 R70.1
PWM_AT: J3.15(A8) R10.1
PWM_BB: J3.9(A5) R17.1 R71.1
PWM_BT: J3.11(A6) R16.1
PWM_CB: J3.5(A3) R19.1 R72.1
PWM_CT: J3.7(A4) R18.1
VM: C1.1(PLUS) C2.1(PLUS) C3.1(PLUS) C28.1 C39.1 D4.A D6.C Q1.9(D2) Q2.9(D2) Q3.9(D2) Q4.1(S1) Q4.2(S2) Q4.3(S3) R33.1 R41.1 TP7.1(TP) U7.2(VIN)
VOLT_DCB: C17.1 J2.7(A4) R33.2 R35.1 TP5.1(TP)
N24033468: C4.1 D3.C U1.20(VB1)
N24033594: C5.1 D2.C U1.16(VB2)
N24033653: C6.1 D1.C U1.10(VB3)
N24035180: D1.A R1.2
N24035201: D2.A R2.2
N24035206: D3.A R7.2
N24035227: Q1.1(G2) R4.2
N24035245: Q1.8(G2) R8.2
N24035263: Q2.1(G2) R5.2
N24035281: Q2.8(G2) R9.2
N24035326: Q3.8(G2) R12.2
N24035327: Q3.1(G2) R6.2
N24038254: C7.2 R20.2 R23.2 U4.3(+INA)
N24038267: C12.1 R26.2 R29.1 U4.2(-INA)
N24039985: C8.2 R21.2 R24.2 U3.3(+INA)
N24039987: C14.1 R27.2 R30.1 U3.2(-INA)
N24040204: C9.2 R22.2 R25.2 U3.5(+INB)
N24040206: C15.1 R28.2 R31.1 U3.6(-INB)
N24055425: C16.1 R32.2 R34.1 U2.3(+INA)
N24056935: R18.2 U1.5(HIN3)
N24056936: R16.2 U1.3(HIN2)
N24056937: R10.2 U1.1(HIN1)
N24056938: R19.2 U1.6(LIN3)
N24056939: R17.2 U1.4(LIN2)
N24056940: R11.2 U1.2(LIN1)
N24071789: C22.2 R37.2 R40.2 U2.5(+INB)
N24071791: C23.1 R38.2 R39.1 U2.6(-INB)
N24077170: C24.1 R47.1 R49.2
N24077180: J8.3 R48.2 R49.1
N24077887: J8.4 R51.2 R52.1
N24077889: C25.1 R50.1 R52.2
N24077981: J8.5 R53.2 R55.1
N24077985: C26.1 R54.1 R55.2
N24134116: U4.6(-INB) U4.7(OUTB)
N24143304: R47.2 U6.1(A)
N24143313: R50.2 U6.3(A)
N24143316: R54.2 U6.5(A)
N24143319: U6.6(Y) U6.9(A)
N24143322: U6.4(Y) U6.11(A)
N24143325: U6.2(Y) U6.13(A)
N24161844: R56.2 R57.1 U5.1(ADJ)
N24161852: C20.1 D4.C U5.3(IN)
N24161961: J6.1 Q4.5(D1) Q4.6(D2) Q4.7(D3) Q4.8(D4)
N24167767: C35.1 U7.1(BOOT)
N24167797: C35.2 D5.C L1.1 U7.10(PH)
N24167831: R46.2 R58.1 U7.7(VSEN)
N24167847: R45.1 U7.5(RT)
N24167851: C36.1 U7.4(SS)
N24167871: C37.1 R59.1 U7.8(COMP)
N24167893: C38.1 R59.2
N24169531: D6.A Q4.4(G) R41.2 R60.1

Not connected (* = marked no-connect by the designer): J1 1(A1) 2(B1) 4(B2) 5(A3) 6(B3) 7(A4) 8(B4) 9(A5) 10(B5) 11(A6) 12(B6) 13(A7) 14(B7) 15(A8) 16(B8); J2 2(B1) 4(B2) 6(B3) 8(B4) 10(B5) 11(A6) 12(B6) 13(A7) 15(A8) 16(B8) 17(A9) 18(B9) 19(A10) 20(B10); J3 2(B1)* 6(B3)* 10(B5); J4 1(A1) 2(B1) 3(A2) 4(B2) 5(A3) 6(B3) 7(A4) 8(B4) 9(A5) 10(B5) 11(A6) 12(B6); U7 3(EN)* 6(PG)*

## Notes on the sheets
sheet 1
- Table of Contents
- Revisions
- 2
- Notes
- Rev
- Description
- Date
- Approved
- 3
- Block Diagram
- X1
- Preliminary Release
- 01/22/2015
- Mario Guardado
- 4
- PMSM Motor Driver
- 5
- Freedom Connectors
- 6
- Power
- FREEDOM PMSM MOTOR DRIVER SHIELD
- OrCAD Capture 16.5
sheet 2
- 1. Unless Otherwise Specified:
- All resistors are in ohms,  1% or 5%, 1/16 Watt
- All capacitors are in uF, 10%, 50V
- All voltages are DC
- All polarized capacitors are aluminum electrolytic
- 2. Interrupted lines coded with the same letter or letter
      combinations are electrically connected.
- 3. Device type number is for reference only. The number
      varies with the manufacturer.
- MCU Peripheral / Port Map
- Function
- MCU Peri
- MCU Port
- 4. Special signal usage:
- _B Denotes - Active-Low Signal
- PWM_AT
- FTM0_CH0
- PTC1
- <> or [] Denotes - Vectored Signals
- PWM_AB
- FTM0_CH1
- PTC2
- 5. Interpret diagram in accordance with American
      National Standards Institute specifications, current
      revision, with the exception of logic block symbology.
- PWM_BT
- FTM0_CH2
- PTC5
- PWM_BB
- FTM0_CH3
- PTC4
- PWM_CT
- FTM0_CH4
- PTD4
- PWM_CB
- FTM0_CH5
- PTD5
- CUR_A
- ADC0_SE8
- PTB0
- CUR_B
- ADC1_DP0
- ADC1_DP0
- CUR_C
- ADC0_DP0
- ADC0_DP0
- VOLT_DCB
- ADC0_SE13
- PTB3
- CUR_DCB
- ADC1_SE18
- ADC1_SE18
- HALL_A / ENC_A
- FTM2_CH0
- PTB18
- HALL_B / ENC_B
- FTM2_CH1
- PTB19
- HALL_C / ENC_I
- FTM1_CH1
- PTA13
sheet 4
- MOSFET Gate Drivers
- Driver Power Stage
- Motor
  Output
- protect inputs when VM is not present
- Note: MOSFET Vgs = 20V max
- ADC Midpoint Reference
- Gain = I * 0.01 * 20k / 1k = 0.2 V/A
- FS Current = 1.65V / 0.2V/A = +/-8.25A
- F = 1/ 2 * Pi * 20k * 10nF = 796Hz
- Ref = 3.3V * 10k / 20k = 1.65V
- F = 1/ 2 * Pi * 10k||10k * 100nF = 318Hz
- Phase and DCB Current Sense
- Gain = VM * 3k / (3k + 52.3k) = 0.054 * VM
- DCB Voltage Sense
- F = 1/ 2 * Pi * 3k||52.3k * 100nF = 561Hz
sheet 5
- Freedom / Arduino Connectors
- Output to MCU card
- Input from MCU card
- Sensor
  Input
- Encoder Inputs
sheet 6
- 15V 10mA
- 48V
  Motor
  Power
  Input
- 36 - 58V
- Iz = 1.5mA @ 48V
- Gate Drivers Power Supply
- 5.5V 500mA
- Output to MCU board
- Output to encoder circuitry
- Base Board Power Supply
